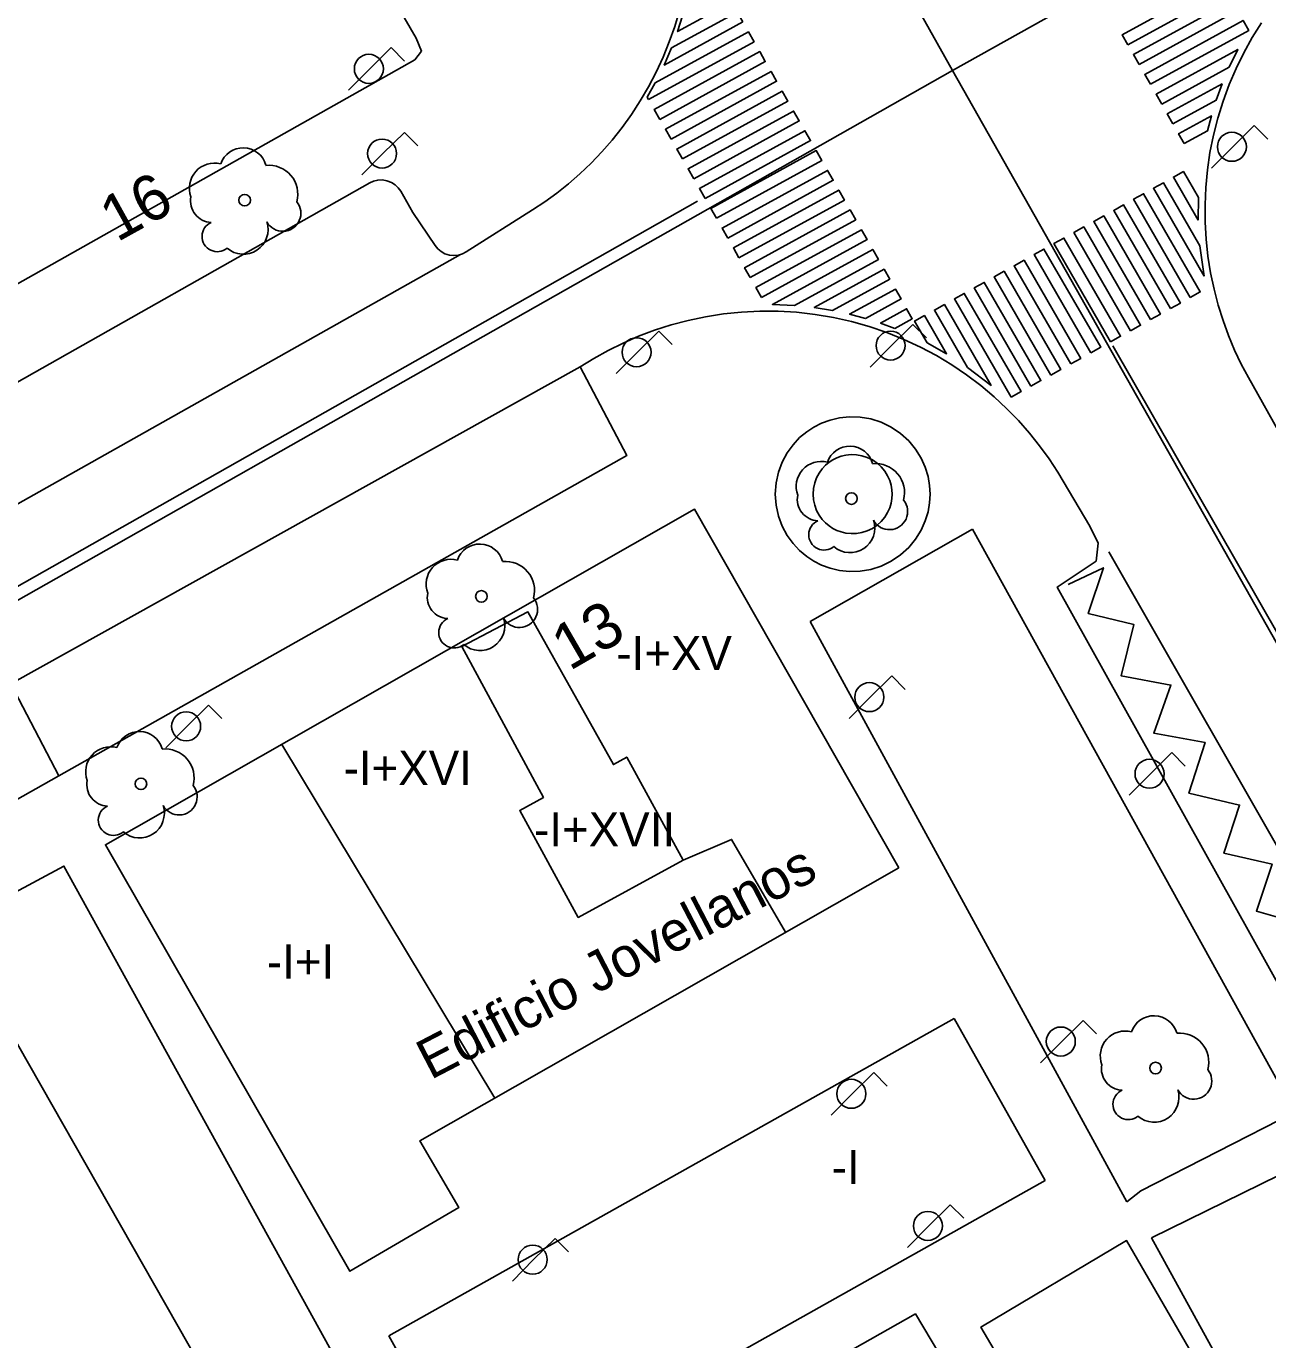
# Model space of a CAD drawing. Extents: x 282771 to 285132, y 4823109 to 4825496.
# Drawn here: x 283706.8 to 283761.3, y 4823546.1 to 4823603.7 of the extents above; entities that cross this region are included whole.
import ezdxf

# ---------------------------------------------------------------- set-up
doc = ezdxf.new("R2010")
doc.units = 0
for name, color, linetype in [('ACERA-BORDILLO', 7, 'Continuous'), ('ACERA-INTERIOR', 7, 'Continuous'), ('ARBOL', 7, 'Continuous'), ('CALLE-EJE', 7, 'Continuous'), ('CARGA_DESCARGA', 7, 'Continuous'), ('EDIFICIO', 7, 'Continuous'), ('FAROLA', 7, 'Continuous'), ('MEDIANERA', 7, 'Continuous'), ('NUM-LOCAL', 7, 'Continuous'), ('NUM-PORTAL', 7, 'Continuous'), ('PASO-PEATONES', 7, 'Continuous'), ('SENAL-VIARIA', 7, 'Continuous'), ('TXT-ALTURA-EDIFICIO', 7, 'Continuous'), ('TXT-EDIFICIOS', 7, 'Continuous'), ('ZONA-VERDE', 7, 'Continuous')]:
    doc.layers.add(name, color=color, linetype=linetype)

msp = doc.modelspace()

# ---------------------------------------------------------------- linework, layer by layer
at = {"layer": 'ACERA-BORDILLO'}
for points in [[(283735.485, 4823604.445), (283735.278, 4823603.746), (283735.037, 4823603.059), (283734.764, 4823602.386), (283734.46, 4823601.729), (283734.127, 4823601.091), (283733.765, 4823600.473), (283733.377, 4823599.877), (283732.965, 4823599.304), (283732.53, 4823598.757), (283732.075, 4823598.235), (283731.602, 4823597.741), (283731.113, 4823597.274), (283730.61, 4823596.835), (283730.095, 4823596.425), (283729.571, 4823596.043), (283729.04, 4823595.69), (283726.125, 4823593.841), (283725.965, 4823593.758), (283725.783, 4823593.704), (283725.586, 4823593.685), (283725.385, 4823593.706), (283725.192, 4823593.767), (283725.019, 4823593.864), (283724.874, 4823593.987), (283724.76, 4823594.127), (283723.782, 4823595.579), (283723.249, 4823596.506), (283723.145, 4823596.655), (283723.006, 4823596.789), (283722.838, 4823596.898), (283722.647, 4823596.972), (283722.444, 4823597.006), (283722.244, 4823596.998), (283722.056, 4823596.953), (283721.89, 4823596.878), (283604.159, 4823530.293)], [(283761.026, 4823603.903), (283760.624, 4823603.258), (283760.252, 4823602.589), (283759.914, 4823601.898), (283759.61, 4823601.187), (283759.342, 4823600.46), (283759.112, 4823599.719), (283758.921, 4823598.968), (283758.769, 4823598.208), (283758.657, 4823597.444), (283758.584, 4823596.677), (283758.551, 4823595.913), (283758.557, 4823595.152), (283758.601, 4823594.399), (283758.681, 4823593.656), (283758.798, 4823592.925), (283758.948, 4823592.209), (283759.131, 4823591.51), (283759.343, 4823590.829), (283759.584, 4823590.17), (283759.852, 4823589.532), (283760.143, 4823588.917), (283760.456, 4823588.326), (283761.961, 4823585.634)], [(283706.14, 4823574.879), (283708.242, 4823570.853), (283733.172, 4823584.906), (283731.128, 4823588.793), (283731.727, 4823589.166), (283732.354, 4823589.516), (283733.008, 4823589.841), (283733.689, 4823590.139), (283734.393, 4823590.406), (283735.121, 4823590.64), (283735.868, 4823590.839), (283736.634, 4823591.001), (283737.415, 4823591.124), (283738.207, 4823591.206), (283739.009, 4823591.245), (283739.817, 4823591.242), (283740.627, 4823591.195), (283741.435, 4823591.104), (283742.239, 4823590.969), (283743.034, 4823590.791), (283743.817, 4823590.57), (283744.585, 4823590.308), (283745.334, 4823590.006), (283746.061, 4823589.666), (283746.764, 4823589.291), (283747.441, 4823588.882), (283748.089, 4823588.444), (283748.706, 4823587.977), (283749.291, 4823587.485), (283749.843, 4823586.972), (283750.361, 4823586.44), (283750.844, 4823585.892), (283751.292, 4823585.331), (283751.706, 4823584.759), (283752.085, 4823584.18), (283753.503, 4823581.804), (283753.856, 4823581.058), (283753.775, 4823580.271), (283752.066, 4823579.132), (283765.542, 4823554.929)], [(283696.213, 4823521.279), (283719.868, 4823535.043), (283717.644, 4823538.956), (283718.386, 4823539.369), (283717.901, 4823540.22), (283721.902, 4823542.519), (283708.47, 4823566.883), (283703.773, 4823564.359)]]:
    msp.add_lwpolyline(points, dxfattribs=at)
at = {"layer": 'ACERA-INTERIOR'}
for points in [[(283746.482, 4823583.213), (283746.461, 4823583.591), (283746.393, 4823583.987), (283746.271, 4823584.393), (283746.09, 4823584.797), (283745.849, 4823585.189), (283745.546, 4823585.555), (283745.188, 4823585.881), (283744.783, 4823586.156), (283744.343, 4823586.369), (283743.882, 4823586.516), (283743.414, 4823586.595), (283742.954, 4823586.608), (283742.513, 4823586.562), (283742.101, 4823586.465), (283741.724, 4823586.327), (283741.386, 4823586.156), (283741.068, 4823585.948), (283740.76, 4823585.691), (283740.47, 4823585.383), (283740.209, 4823585.024), (283739.991, 4823584.618), (283739.825, 4823584.174), (283739.722, 4823583.701), (283739.687, 4823583.213), (283739.722, 4823582.725), (283739.825, 4823582.252), (283739.991, 4823581.807), (283740.209, 4823581.402), (283740.47, 4823581.043), (283740.76, 4823580.735), (283741.068, 4823580.478), (283741.386, 4823580.27), (283741.724, 4823580.099), (283742.101, 4823579.96), (283742.513, 4823579.863), (283742.954, 4823579.818), (283743.414, 4823579.831), (283743.882, 4823579.91), (283744.343, 4823580.057), (283744.783, 4823580.27), (283745.188, 4823580.545), (283745.546, 4823580.871), (283745.849, 4823581.237), (283746.09, 4823581.628), (283746.271, 4823582.033), (283746.393, 4823582.439), (283746.461, 4823582.834), (283746.482, 4823583.213)], [(283744.821, 4823583.213), (283744.81, 4823583.406), (283744.775, 4823583.609), (283744.713, 4823583.816), (283744.62, 4823584.022), (283744.497, 4823584.223), (283744.342, 4823584.41), (283744.159, 4823584.576), (283743.953, 4823584.716), (283743.728, 4823584.825), (283743.492, 4823584.9), (283743.253, 4823584.941), (283743.018, 4823584.948), (283742.793, 4823584.924), (283742.582, 4823584.875), (283742.389, 4823584.804), (283742.217, 4823584.716), (283742.054, 4823584.61), (283741.897, 4823584.479), (283741.749, 4823584.321), (283741.616, 4823584.138), (283741.504, 4823583.931), (283741.419, 4823583.704), (283741.367, 4823583.462), (283741.349, 4823583.213), (283741.367, 4823582.964), (283741.419, 4823582.722), (283741.504, 4823582.495), (283741.616, 4823582.288), (283741.749, 4823582.104), (283741.897, 4823581.947), (283742.054, 4823581.816), (283742.217, 4823581.71), (283742.389, 4823581.622), (283742.582, 4823581.551), (283742.793, 4823581.502), (283743.018, 4823581.478), (283743.253, 4823581.485), (283743.492, 4823581.525), (283743.728, 4823581.6), (283743.953, 4823581.71), (283744.159, 4823581.85), (283744.342, 4823582.016), (283744.497, 4823582.203), (283744.62, 4823582.403), (283744.713, 4823582.61), (283744.775, 4823582.817), (283744.81, 4823583.02), (283744.821, 4823583.213)], [(283708.242, 4823570.853), (283702.148, 4823567.412)]]:
    msp.add_lwpolyline(points, dxfattribs=at)
at = {"layer": 'ARBOL'}
for centre in [(283716.401, 4823596.116), (283743.032, 4823583.019), (283726.79, 4823578.724), (283711.849, 4823570.495), (283756.382, 4823558.019)]:
    msp.add_circle(centre, 0.255, dxfattribs=at)
for centre, radius, start, end in [((283716.331, 4823597.376), 1.038, 15.64228, 161.38435), ((283715.071, 4823596.646), 1.097, 75.4318, 200.55608), ((283717.461, 4823596.376), 1.272, 345.03273, 95.79925), ((283714.961, 4823596.076), 0.935, 168.59898, 268.13236), ((283718.071, 4823595.546), 0.797, 208.96246, 38.99103), ((283715.201, 4823594.526), 0.672, 113.73672, 309.4725), ((283716.341, 4823594.826), 1.086, 228.95447, 17.92796), ((283742.962, 4823584.279), 1.038, 15.64228, 161.38435), ((283741.702, 4823583.549), 1.097, 75.4318, 200.55608), ((283744.092, 4823583.279), 1.272, 345.03273, 95.79925), ((283741.592, 4823582.979), 0.935, 168.59898, 268.13236), ((283744.702, 4823582.449), 0.797, 208.96246, 38.99103), ((283741.832, 4823581.429), 0.672, 113.73672, 309.4725), ((283742.972, 4823581.729), 1.086, 228.95447, 17.92796), ((283726.72, 4823579.984), 1.038, 15.64228, 161.38435), ((283725.46, 4823579.254), 1.097, 75.4318, 200.55608), ((283727.85, 4823578.984), 1.272, 345.03273, 95.79925), ((283725.35, 4823578.684), 0.935, 168.59898, 268.13236), ((283728.46, 4823578.154), 0.797, 208.96246, 38.99103), ((283725.59, 4823577.134), 0.672, 113.73672, 309.4725), ((283726.73, 4823577.434), 1.086, 228.95447, 17.92796), ((283711.779, 4823571.755), 1.038, 15.64228, 161.38435), ((283710.519, 4823571.025), 1.097, 75.4318, 200.55608), ((283712.909, 4823570.755), 1.272, 345.03273, 95.79925), ((283710.409, 4823570.455), 0.935, 168.59898, 268.13236), ((283713.519, 4823569.925), 0.797, 208.96246, 38.99103), ((283710.649, 4823568.905), 0.672, 113.73672, 309.4725), ((283711.789, 4823569.205), 1.086, 228.95447, 17.92796), ((283756.312, 4823559.279), 1.038, 15.64228, 161.38435), ((283755.052, 4823558.549), 1.097, 75.4318, 200.55608), ((283757.442, 4823558.279), 1.272, 345.03273, 95.79925), ((283754.942, 4823557.979), 0.935, 168.59898, 268.13236), ((283758.052, 4823557.449), 0.797, 208.96246, 38.99103), ((283755.182, 4823556.429), 0.672, 113.73672, 309.4725), ((283756.322, 4823556.729), 1.086, 228.95447, 17.92796)]:
    msp.add_arc(centre, radius, start, end, dxfattribs=at)
at = {"layer": 'CALLE-EJE'}
for points in [[(283747.472, 4823601.808), (283685.293, 4823712.647)], [(283904.71, 4823689.628), (283747.472, 4823601.808)], [(283747.472, 4823601.808), (283590.524, 4823512.859)], [(283805.222, 4823499.78), (283747.472, 4823601.808)]]:
    msp.add_lwpolyline(points, dxfattribs=at)
at = {"layer": 'CARGA_DESCARGA'}
msp.add_lwpolyline([(283752.549, 4823579.248), (283754.092, 4823579.984), (283753.427, 4823577.966), (283755.42, 4823577.492), (283754.875, 4823575.236), (283757.058, 4823574.833), (283756.298, 4823572.72), (283758.553, 4823572.316), (283757.841, 4823570.085), (283760.071, 4823569.563), (283759.383, 4823567.45), (283761.495, 4823566.975), (283760.807, 4823564.91), (283763.061, 4823564.269)], dxfattribs=at)
at = {"layer": 'EDIFICIO'}
for points in [[(283745.112, 4823566.815), (283724.092, 4823554.829), (283725.802, 4823551.899), (283721.022, 4823549.099), (283710.292, 4823567.819), (283736.142, 4823582.559), (283745.112, 4823566.815)], [(283729.992, 4823539.169), (283737.172, 4823543.399), (283737.902, 4823542.159), (283738.942, 4823542.639), (283738.762, 4823543.219), (283745.842, 4823547.229), (283747.582, 4823544.309), (283749.442, 4823545.409), (283748.712, 4823546.649), (283755.112, 4823550.449), (283760.262, 4823541.549), (283759.552, 4823541.139), (283760.262, 4823539.929), (283760.952, 4823540.329), (283763.722, 4823535.479)]]:
    msp.add_lwpolyline(points, dxfattribs=at)
at = {"layer": 'FAROLA'}
for p, q in [((283722.831, 4823602.811), (283721.891, 4823601.881)), ((283723.421, 4823602.221), (283722.831, 4823602.811)), ((283721.891, 4823601.881), (283720.961, 4823600.941)), ((283723.411, 4823599.091), (283722.471, 4823598.161)), ((283724.001, 4823598.501), (283723.411, 4823599.091)), ((283760.712, 4823599.389), (283759.772, 4823598.459)), ((283761.302, 4823598.799), (283760.712, 4823599.389)), ((283759.772, 4823598.459), (283758.842, 4823597.519)), ((283722.471, 4823598.161), (283721.541, 4823597.221)), ((283734.581, 4823590.371), (283733.641, 4823589.441)), ((283735.171, 4823589.781), (283734.581, 4823590.371)), ((283745.731, 4823590.661), (283744.791, 4823589.731)), ((283746.321, 4823590.071), (283745.731, 4823590.661)), ((283744.791, 4823589.731), (283743.861, 4823588.791)), ((283733.641, 4823589.441), (283732.711, 4823588.501)), ((283744.799, 4823575.231), (283743.859, 4823574.301)), ((283745.389, 4823574.641), (283744.799, 4823575.231)), ((283743.859, 4823574.301), (283742.929, 4823573.361)), ((283714.811, 4823573.95), (283713.871, 4823573.02)), ((283715.401, 4823573.36), (283714.811, 4823573.95)), ((283713.871, 4823573.02), (283712.941, 4823572.081)), ((283757.096, 4823571.868), (283756.156, 4823570.938)), ((283757.686, 4823571.278), (283757.096, 4823571.868)), ((283756.156, 4823570.938), (283755.226, 4823569.998)), ((283753.201, 4823560.113), (283752.261, 4823559.183)), ((283753.791, 4823559.523), (283753.201, 4823560.113)), ((283752.261, 4823559.183), (283751.331, 4823558.243)), ((283744.008, 4823557.82), (283743.068, 4823556.89)), ((283744.598, 4823557.23), (283744.008, 4823557.82)), ((283743.068, 4823556.89), (283742.138, 4823555.95)), ((283747.369, 4823552.019), (283746.429, 4823551.089)), ((283747.959, 4823551.429), (283747.369, 4823552.019)), ((283746.429, 4823551.089), (283745.499, 4823550.149)), ((283730.022, 4823550.539), (283729.082, 4823549.609)), ((283730.612, 4823549.949), (283730.022, 4823550.539)), ((283729.082, 4823549.609), (283728.152, 4823548.669))]:
    msp.add_line(p, q, dxfattribs=at)
for centre in [(283721.851, 4823601.881), (283759.732, 4823598.459), (283722.431, 4823598.161), (283744.751, 4823589.731), (283733.601, 4823589.441), (283743.819, 4823574.301), (283713.831, 4823573.02), (283756.116, 4823570.938), (283752.221, 4823559.183), (283743.028, 4823556.89), (283746.389, 4823551.089), (283729.042, 4823549.609)]:
    msp.add_circle(centre, 0.637, dxfattribs=at)
at = {"layer": 'MEDIANERA'}
for points in [[(283735.652, 4823567.149), (283733.172, 4823571.669), (283732.582, 4823571.339), (283728.832, 4823578.039), (283725.932, 4823576.519), (283729.512, 4823569.899), (283728.472, 4823569.329), (283731.042, 4823564.629), (283735.652, 4823567.149), (283737.772, 4823568.059), (283740.137, 4823563.978)], [(283718.032, 4823572.229), (283727.374, 4823556.7)]]:
    msp.add_lwpolyline(points, dxfattribs=at)
at = {"layer": 'PASO-PEATONES'}
for points in [[(283737.765, 4823604.806), (283735.405, 4823603.513), (283735.624, 4823604.203), (283737.517, 4823605.24)], [(283755.161, 4823602.939), (283754.912, 4823603.373), (283759.23, 4823605.74), (283759.478, 4823605.306)], [(283755.657, 4823602.071), (283755.409, 4823602.505), (283759.726, 4823604.872), (283759.974, 4823604.438)], [(283738.261, 4823603.938), (283734.816, 4823602.049), (283735.139, 4823602.796), (283738.013, 4823604.372)], [(283734.127, 4823600.531), (283734.068, 4823600.634), (283734.425, 4823601.264), (283738.509, 4823603.504), (283738.757, 4823603.07)], [(283756.153, 4823601.202), (283755.905, 4823601.636), (283760.222, 4823604.003), (283760.47, 4823603.569)], [(283734.623, 4823599.663), (283734.375, 4823600.097), (283739.005, 4823602.635), (283739.253, 4823602.201)], [(283756.649, 4823600.334), (283756.401, 4823600.768), (283759.991, 4823602.736), (283759.611, 4823601.958)], [(283735.119, 4823598.794), (283734.871, 4823599.228), (283739.502, 4823601.767), (283739.75, 4823601.333)], [(283757.145, 4823599.466), (283756.897, 4823599.9), (283759.299, 4823601.216), (283759.041, 4823600.505)], [(283735.616, 4823597.926), (283735.367, 4823598.36), (283739.998, 4823600.899), (283740.246, 4823600.465)], [(283736.112, 4823597.058), (283735.864, 4823597.492), (283740.494, 4823600.03), (283740.742, 4823599.596)], [(283757.642, 4823598.597), (283757.394, 4823599.031), (283758.829, 4823599.818), (283758.656, 4823599.154)], [(283736.608, 4823596.189), (283736.36, 4823596.623), (283740.99, 4823599.162), (283741.238, 4823598.728)], [(283737.104, 4823595.321), (283736.856, 4823595.755), (283741.486, 4823598.294), (283741.735, 4823597.859)], [(283737.6, 4823594.453), (283737.352, 4823594.887), (283741.983, 4823597.425), (283742.231, 4823596.991)], [(283758.254, 4823595.239), (283757.164, 4823597.127), (283757.601, 4823597.37), (283758.26, 4823596.229)], [(283738.097, 4823593.584), (283737.849, 4823594.018), (283742.479, 4823596.557), (283742.727, 4823596.123)], [(283758.52, 4823592.78), (283756.29, 4823596.64), (283756.727, 4823596.884), (283758.326, 4823594.116)], [(283757.906, 4823591.844), (283755.416, 4823596.154), (283755.853, 4823596.397), (283758.343, 4823592.087)], [(283738.593, 4823592.716), (283738.345, 4823593.15), (283742.975, 4823595.689), (283743.223, 4823595.254)], [(283756.157, 4823590.872), (283753.668, 4823595.182), (283754.105, 4823595.425), (283756.594, 4823591.115)], [(283757.031, 4823591.358), (283754.542, 4823595.668), (283754.979, 4823595.911), (283757.469, 4823591.601)], [(283739.089, 4823591.847), (283738.841, 4823592.282), (283743.471, 4823594.82), (283743.719, 4823594.386)], [(283755.283, 4823590.386), (283752.794, 4823594.696), (283753.231, 4823594.939), (283755.72, 4823590.629)], [(283754.41, 4823589.9), (283751.92, 4823594.21), (283752.357, 4823594.453), (283754.846, 4823590.143)], [(283740.528, 4823591.496), (283739.567, 4823591.539), (283743.968, 4823593.952), (283744.216, 4823593.518)], [(283753.536, 4823589.413), (283751.046, 4823593.724), (283751.483, 4823593.967), (283753.973, 4823589.657)], [(283742.203, 4823591.274), (283741.4, 4823591.404), (283744.464, 4823593.083), (283744.712, 4823592.649)], [(283752.662, 4823588.927), (283750.172, 4823593.237), (283750.609, 4823593.48), (283753.099, 4823589.17)], [(283750.913, 4823587.955), (283748.424, 4823592.265), (283748.861, 4823592.508), (283751.35, 4823588.198)], [(283751.787, 4823588.441), (283749.298, 4823592.751), (283749.735, 4823592.994), (283752.224, 4823588.684)], [(283743.65, 4823590.927), (283742.95, 4823591.113), (283744.96, 4823592.215), (283745.208, 4823591.781)], [(283750.039, 4823587.469), (283747.55, 4823591.779), (283747.987, 4823592.022), (283750.476, 4823587.712)], [(283744.933, 4823590.489), (283744.309, 4823590.718), (283745.456, 4823591.347), (283745.704, 4823590.912)], [(283748.128, 4823588.778), (283746.676, 4823591.293), (283747.113, 4823591.536), (283749.163, 4823587.987)], [(283746.356, 4823589.847), (283745.802, 4823590.807), (283746.239, 4823591.05), (283747.206, 4823589.375)]]:
    msp.add_lwpolyline(points, close=True, dxfattribs=at)
at = {"layer": 'SENAL-VIARIA'}
for points in [[(283736.269, 4823596.07), (283719.492, 4823586.556)], [(283725.874, 4823593.731), (283604.69, 4823525.475)], [(283754.505, 4823589.726), (283762.739, 4823575.34)], [(283731.128, 4823588.793), (283706.14, 4823574.879)], [(283719.492, 4823586.556), (283607.092, 4823522.878)], [(283789.447, 4823519.245), (283754.326, 4823580.679)], [(283703.943, 4823563.413), (283716.443, 4823541.477)]]:
    msp.add_lwpolyline(points, dxfattribs=at)
at = {"layer": 'ZONA-VERDE'}
for p, q in [((283710.522, 4823626.571), (283723.921, 4823603.231)), ((283723.921, 4823603.231), (283724.161, 4823602.651)), ((283724.161, 4823602.651), (283723.871, 4823602.271)), ((283723.871, 4823602.271), (283696.634, 4823586.928)), ((283741.221, 4823577.621), (283748.341, 4823581.671)), ((283748.341, 4823581.671), (283762.491, 4823556.081)), ((283755.121, 4823552.141), (283741.221, 4823577.621)), ((283722.722, 4823546.259), (283747.542, 4823560.199)), ((283747.542, 4823560.199), (283751.542, 4823553.089)), ((283762.491, 4823556.081), (283755.741, 4823552.631)), ((283756.201, 4823550.571), (283763.591, 4823554.201)), ((283751.542, 4823553.089), (283726.722, 4823539.149)), ((283755.741, 4823552.631), (283755.121, 4823552.141)), ((283769.241, 4823526.851), (283756.201, 4823550.571)), ((283726.722, 4823539.149), (283722.722, 4823546.259))]:
    msp.add_line(p, q, dxfattribs=at)

# ---------------------------------------------------------------- texts
at = {"layer": 'NUM-LOCAL'}
msp.add_text('16', height=2, rotation=28.96004, dxfattribs=at).set_placement((283710.796, 4823594.252))
at = {"layer": 'NUM-PORTAL'}
msp.add_text('13', height=2, rotation=30.05004, dxfattribs=at).set_placement((283730.655, 4823575.43))
at = {"layer": 'TXT-ALTURA-EDIFICIO'}
for s, p in [('-I+XV', (283732.716, 4823575.489)), ('-I+XVI', (283720.746, 4823570.449)), ('-I+XVII', (283729.105, 4823567.749)), ('-I+I', (283717.379, 4823561.949)), ('-I', (283742.168, 4823552.929))]:
    msp.add_text(s, height=1.5, rotation=0.00004, dxfattribs=at).set_placement(p)
at = {"layer": 'TXT-EDIFICIOS'}
msp.add_text('Edificio Jovellanos', height=1.75, rotation=27.47795, dxfattribs=at).set_placement((283724.559, 4823557.483))

doc.saveas('drawing.dxf')
